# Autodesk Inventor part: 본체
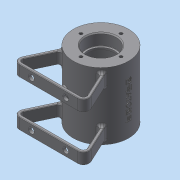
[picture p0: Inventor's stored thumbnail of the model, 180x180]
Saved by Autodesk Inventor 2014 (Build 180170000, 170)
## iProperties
Created: 2021-12
Part Number: 본체
Material: 일반
Document SubType Name: Modeling
Designer: dg
Density: 1 g/cm^3
Appearance: 기본값
Author: dg
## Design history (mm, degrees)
sketch "스케치1"
  geometry: C1 r 29 at (0, 0); 1 further point
  constraints: 1 centre point, 1 coincident
  dimensions: "d0" = 58 diameter of C1
extrude "돌출1" new body sketch "스케치1" stored distance "d1" = 70; taper "d2" = 0 deg
node "작업 평면1"
sketch "스케치2"
  geometry: C1 r 5 at (0, 0); 1 further point
  constraints: 1 centre point, 1 coincident
  dimensions: "d4" = 10 diameter of C1
extrude "돌출2" join sketch "스케치2" stored distance "d5" = 70; taper "d6" = 0 deg
sketch "스케치3"
  geometry: L1 (0, 0)-(-10.945, -30.07); L2 (0, 0)-(0, -42.067)
  constraints: 4 end point, 1 vertical
  dimensions: "d7" = 20 deg angle of L2 L1; "d8" = 32 distance of L1.start L1.end
node "작업 평면2"
sketch "스케치4"
  geometry: C1 r 6 at (0, 0); 1 further point
  constraints: 1 centre point, 1 coincident
  dimensions: "d9" = 12 diameter of C1
extrude "돌출3" join sketch "스케치4" stored distance "d10" = 70; taper "d11" = 0 deg
node "작업 평면3"
sketch "스케치6"
  geometry: L1 (-22.743, -17.993)-(-40, -55); L2 (-40, -55)-(40, -55); L3 (40, -55)-(22.743, -17.993); L4 (-20.574, -20.438)-(-35.291, -52); L5 (-35.291, -52)-(35.291, -52); L6 (35.291, -52)-(20.574, -20.438); A1 r 29 centre (0, 0) between (-22.743, -17.993) and (22.743, -17.993) reference; 1 further point
  constraints: 12 end point, 4 point on circle, 1 horizontal
  dimensions: "d13" = 80 distance of L1.end L2.end; "d14" = 40 horizontal distance of point (0, 0) L1.end; "d15" = 55 distance from line of point (0, 0) L2; "d16" = 65 deg angle of L2 L1; "d17" = 65 deg angle of L2 L3; "d18" = 3 distance between parallel lines of L1 L4; "d19" = 3 distance between parallel lines of L3 L6; "d20" = 3 distance between parallel lines of L2 L5
extrude "돌출4" join sketch "스케치6" distance "d21" = 12; taper "d22" = 0 deg
fillet "모깎기1" dims "d23" = 6
fillet "모깎기2" dims "d24" = 3
fillet "모깎기3" dims "d25" = 0.5
fillet "모깎기4" dims "d26" = 3
sketch "스케치7"
  geometry: L1 (0, -11.5)-(61.164, -11.5) reference; C1 r 3 at (12.582, -5.5); C2 r 3 at (48.582, -5.5); 1 further point
  constraints: 2 centre point, 1 equal radius, 1 horizontal alignment
  dimensions: "d27" = 36 distance of C2.centre C1.centre; "d28" = 18 horizontal distance of C1.centre point (30.582, 18.5); "d29" = 6 distance from line of L1 C1.centre; "d30" = 6 diameter of C1
extrude "돌출5" cut sketch "스케치7" stored distance "d31" = 12; taper "d32" = 0 deg
sketch "스케치8"
  geometry: L1 (29, 35)-(-29, 35) reference; L2 (-29, -35)-(29, -35) reference; L3 (0, 35)-(0, -35); L4 (0, 35)-(16, 35); L5 (16, 35)-(16, 23); L6 (16, 23)-(14, 23); L7 (14, 23)-(14, 21); L8 (14, 21)-(21, 21); L9 (21, 21)-(21, -21); L10 (21, -21)-(14, -21); L11 (14, -21)-(14, -23); L12 (14, -23)-(16, -23); L13 (16, -23)-(16, -35); L14 (16, -35)-(0, -35); 1 further point
  constraints: 24 end point, 6 parallel, 3 perpendicular, 2 midpoint, 2 point on line, 1 collinear
  dimensions: "d33" = 32 diameter of L5 L3; "d34" = 28 diameter of L7 L3; "d35" = 12 distance of L4.end L5.end; "d36" = 42 distance of L8.end L9.end; "d37" = 2 distance between parallel lines of L12 L10; "d38" = 12 distance of L12.end L13.end; "d39" = 42 diameter of L9 L3; "d40" = 28 diameter of L11 L3; "d41" = 32 diameter of L13 L3
revolve "회전1" sketch "스케치8" stored, may be unused: angle "d42" = 90 deg
hole "구멍1" diameter "d45" = 3; stored, may be unused: countersink angle "d49" = 90 deg, drill point angle "d51" = 118 deg; dims "d43" = 10, "d44" = 10, "d46" = 6, "d47" = 4, "d48" = 2, "d50" = 8
hole "구멍2" diameter "d54" = 5.188; stored, may be unused: countersink angle "d58" = 90 deg, drill point angle "d60" = 118 deg; dims "d52" = 10, "d53" = 10, "d55" = 6, "d56" = 4, "d57" = 2, "d59" = 8
hole "구멍3" diameter "d63" = 5.188; stored, may be unused: countersink angle "d67" = 90 deg, drill point angle "d69" = 118 deg; dims "d61" = 10, "d62" = 10, "d64" = 100, "d65" = 4, "d66" = 2, "d68" = 8
fillet "모깎기5" dims "d70" = 1, "d71" = 0.3, "d72" = 3
chamfer "모따기1" distance "d73" = 1; stored, may be unused: second distance "d74" = 2, angle "d75" = 45 deg
sketch "스케치9"
  geometry: C1 r 29 at (0, 0) reference; 1 further point
  constraints: 1 vertical alignment
  dimensions: "d76" = 21 distance of C1.centre point (0, 21)
hole "구멍4" sketch "스케치9" at (0, 21) diameter "d77" = 3.242; stored, may be unused: countersink angle "d81" = 90 deg, drill point angle "d83" = 118 deg; dims "d78" = 8, "d79" = 4, "d80" = 2, "d82" = 10
node "작업 평면4"
sketch "스케치10"
  geometry: L1 (29, 35)-(-29, 35) reference; L2 (29, -35)-(29, 35) reference; 2 further points
  constraints: 1 other
  dimensions: "d87" = 35 distance from line of point (0, 0) L1; "d88" = 29 distance from line of point (0, 0) L2
feature "엠보싱1" sketch "스케치10" dims "d2" = 0, "d13" = 80, "d14" = 40, "d15" = 55, "d16" = 65 deg, "d17" = 65 deg, "d18" = 3, "d19" = 3, "d20" = 3, "d89" = 0.5, "d90" = 0
node "솔리드1"
mirror "대칭1"
pattern_circular "원형 패턴1" dims angle "d85" = 360 deg
mirror "대칭2"
node "투영된 루프1"
other parameters: "d3" = 32, "d12" = 18
